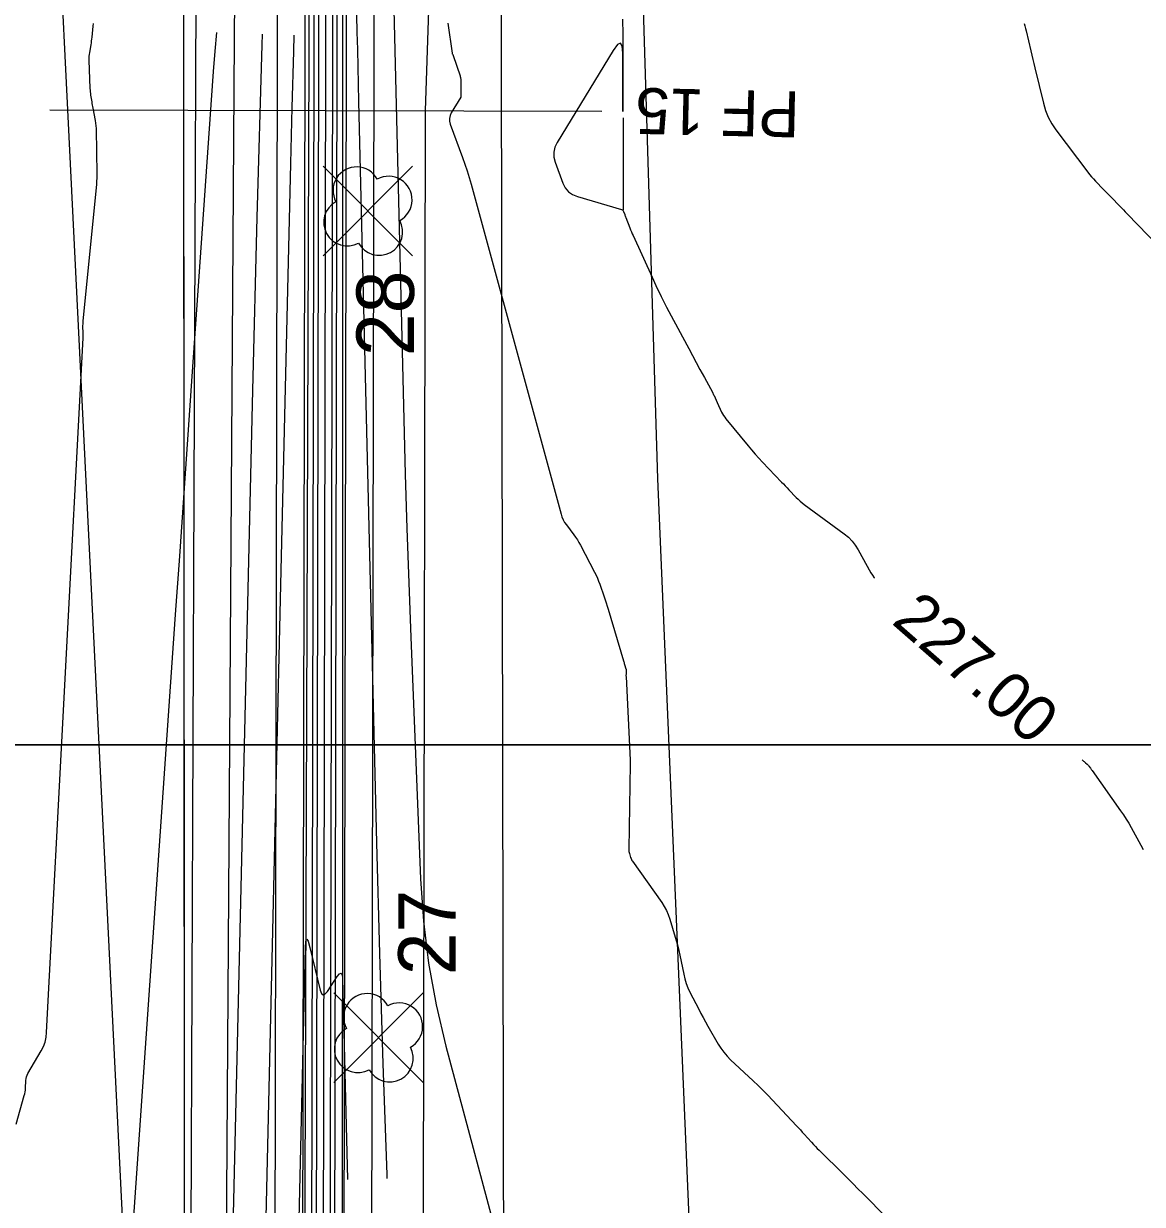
# Model space of a CAD drawing. Extents: x -534410 to -534262, y -1190162 to -1189584.
# Drawn here: x -534372.95 to -534348.63, y -1189804.46 to -1189778.79 of the extents above; entities that cross this region are included whole.
import ezdxf

# ---------------------------------------------------------------- set-up
doc = ezdxf.new("R2010")
doc.units = 0
for name, color, linetype in [('30', 7, 'Continuous'), ('31', 7, 'Continuous'), ('40', 7, 'Continuous'), ('_linie', 7, 'Continuous'), ('_N_osa', 7, 'Continuous'), ('_N_tenká', 7, 'Continuous'), ('_N_tenká_velmi', 7, 'Continuous'), ('_N_text', 7, 'Continuous'), ('_přístup', 7, 'Continuous'), ('_rámeček', 7, 'Continuous'), ('_tenka', 7, 'Continuous'), ('Default', 7, 'Continuous'), ('Hranice parcel', 7, 'Continuous')]:
    doc.layers.add(name, color=color, linetype=linetype)

msp = doc.modelspace()

# ---------------------------------------------------------------- linework, layer by layer
at = {"layer": '30'}
for points in [[(-534364.917, -1189777.897), (-534364.89, -1189779.084), (-534364.863, -1189780.271), (-534364.835, -1189781.459), (-534364.806, -1189782.646), (-534364.69, -1189787.402), (-534364.659, -1189788.586), (-534364.623, -1189789.769), (-534364.583, -1189790.952), (-534364.538, -1189792.135), (-534364.327, -1189797.385), (-534364.264, -1189798.305), (-534364.151, -1189799.218), (-534363.988, -1189800.123), (-534363.773, -1189801.02), (-534362.475, -1189805.863)], [(-534373.119, -1189802.721), (-534372.939, -1189802.098), (-534372.929, -1189802.057), (-534372.921, -1189802.017), (-534372.916, -1189801.976), (-534372.913, -1189801.935), (-534372.906, -1189801.768), (-534372.902, -1189801.728), (-534372.893, -1189801.688), (-534372.879, -1189801.65), (-534372.86, -1189801.614), (-534372.574, -1189801.126), (-534372.525, -1189801.031), (-534372.489, -1189800.933), (-534372.465, -1189800.83), (-534372.453, -1189800.724), (-534371.663, -1189785.627), (-534371.661, -1189785.597), (-534371.661, -1189785.567), (-534371.66, -1189785.537), (-534371.661, -1189785.507), (-534371.664, -1189785.386), (-534371.664, -1189785.356), (-534371.663, -1189785.326), (-534371.662, -1189785.296), (-534371.659, -1189785.266), (-534371.365, -1189782.288), (-534371.359, -1189782.22), (-534371.356, -1189782.153), (-534371.354, -1189782.085), (-534371.354, -1189782.017), (-534371.362, -1189781.623), (-534371.362, -1189781.597), (-534371.363, -1189781.558), (-534371.363, -1189781.545), (-534371.371, -1189781.129), (-534371.373, -1189781.072), (-534371.378, -1189781.015), (-534371.385, -1189780.959), (-534371.394, -1189780.902), (-534371.442, -1189780.635), (-534371.448, -1189780.6), (-534371.455, -1189780.564), (-534371.461, -1189780.529), (-534371.467, -1189780.493), (-534371.491, -1189780.351), (-534371.496, -1189780.316), (-534371.5, -1189780.28), (-534371.503, -1189780.244), (-534371.505, -1189780.208), (-534371.529, -1189779.589), (-534371.53, -1189779.547), (-534371.528, -1189779.505), (-534371.524, -1189779.463), (-534371.518, -1189779.421), (-534371.488, -1189779.255), (-534371.481, -1189779.213), (-534371.475, -1189779.172), (-534371.469, -1189779.13), (-534371.465, -1189779.088), (-534371.442, -1189778.847), (-534371.437, -1189778.793)], [(-534359.934, -1189778.7), (-534359.932, -1189778.799), (-534359.931, -1189778.844), (-534359.93, -1189778.89), (-534359.927, -1189778.982), (-534359.927, -1189779.005), (-534359.926, -1189779.028), (-534359.926, -1189779.05), (-534359.926, -1189779.073), (-534359.926, -1189780.616), (-534359.926, -1189780.639), (-534359.926, -1189780.661), (-534359.925, -1189780.684), (-534359.925, -1189780.707), (-534359.925, -1189780.684), (-534359.926, -1189780.661), (-534359.926, -1189780.639), (-534359.926, -1189780.616), (-534359.926, -1189779.436), (-534359.939, -1189779.279), (-534359.979, -1189779.217), (-534360.045, -1189779.249), (-534360.138, -1189779.377), (-534361.354, -1189781.377), (-534361.404, -1189781.481), (-534361.427, -1189781.588), (-534361.425, -1189781.697), (-534361.396, -1189781.809), (-534361.229, -1189782.262), (-534361.178, -1189782.365), (-534361.109, -1189782.448), (-534361.021, -1189782.512), (-534360.915, -1189782.555), (-534359.955, -1189782.835), (-534359.94, -1189782.841), (-534359.927, -1189782.85), (-534359.917, -1189782.862), (-534359.91, -1189782.877), (-534359.887, -1189782.943), (-534359.881, -1189782.96), (-534359.875, -1189782.976), (-534359.869, -1189782.993), (-534359.862, -1189783.009), (-534359.776, -1189783.234), (-534359.759, -1189783.277), (-534359.742, -1189783.319), (-534359.724, -1189783.362), (-534359.705, -1189783.403), (-534359.29, -1189784.304), (-534359.207, -1189784.484), (-534359.096, -1189784.724), (-534359.068, -1189784.784), (-534359.039, -1189784.844), (-534359.009, -1189784.903), (-534358.978, -1189784.961), (-534358.632, -1189785.602), (-534358.494, -1189785.858), (-534358.25, -1189786.31), (-534358.154, -1189786.488), (-534357.981, -1189786.808), (-534357.972, -1189786.826), (-534357.962, -1189786.845), (-534357.953, -1189786.863), (-534357.945, -1189786.882), (-534357.876, -1189787.032), (-534357.781, -1189787.238), (-534357.761, -1189787.278), (-534357.738, -1189787.317), (-534357.713, -1189787.353), (-534357.686, -1189787.389), (-534357.205, -1189787.971), (-534357.128, -1189788.062), (-534357.05, -1189788.152), (-534356.97, -1189788.24), (-534356.889, -1189788.327), (-534356.477, -1189788.761), (-534356.437, -1189788.802), (-534356.398, -1189788.844), (-534356.357, -1189788.886), (-534356.317, -1189788.928), (-534356.156, -1189789.094), (-534356.115, -1189789.135), (-534356.073, -1189789.174), (-534356.029, -1189789.211), (-534355.983, -1189789.246), (-534355.114, -1189789.888), (-534355.024, -1189789.961), (-534354.944, -1189790.043), (-534354.873, -1189790.133), (-534354.812, -1189790.231), (-534354.533, -1189790.732), (-534354.5, -1189790.787), (-534354.463, -1189790.839), (-534354.454, -1189790.851)], [(-534368.572, -1189812.408), (-534367.974, -1189786.766), (-534367.879, -1189783.012), (-534367.771, -1189779.259), (-534367.763, -1189779.023)], [(-534359.922, -1189780.845), (-534359.922, -1189782.845)], [(-534349.938, -1189794.801), (-534349.91, -1189794.827), (-534349.9, -1189794.836), (-534349.891, -1189794.844), (-534349.881, -1189794.853), (-534349.871, -1189794.861), (-534349.831, -1189794.895), (-534349.821, -1189794.904), (-534349.812, -1189794.913), (-534349.803, -1189794.923), (-534349.795, -1189794.933), (-534349.76, -1189794.981), (-534349.752, -1189794.992), (-534349.743, -1189795.004), (-534349.735, -1189795.015), (-534349.727, -1189795.027), (-534349.106, -1189795.905), (-534349.045, -1189795.995), (-534348.986, -1189796.086), (-534348.93, -1189796.178), (-534348.877, -1189796.273), (-534348.669, -1189796.654), (-534348.614, -1189796.748)], [(-534367.679, -1189830.441), (-534367.447, -1189823.822), (-534367.391, -1189822.167), (-534367.34, -1189820.512), (-534367.294, -1189818.856), (-534367.253, -1189817.201), (-534366.829, -1189798.889), (-534366.819, -1189798.744), (-534366.799, -1189798.695), (-534366.77, -1189798.739), (-534366.73, -1189798.878), (-534366.506, -1189799.806), (-534366.479, -1189799.878), (-534366.444, -1189799.907), (-534366.402, -1189799.892), (-534366.351, -1189799.834), (-534366.134, -1189799.511), (-534366.086, -1189799.452), (-534366.051, -1189799.438), (-534366.029, -1189799.469), (-534366.02, -1189799.544), (-534365.914, -1189803.919)]]:
    msp.add_lwpolyline(points, dxfattribs=at)
at = {"layer": '31'}
for points in [[(-534365.74, -1189777.481), (-534365.707, -1189778.983), (-534365.698, -1189779.359), (-534365.689, -1189779.735), (-534365.68, -1189780.11), (-534365.671, -1189780.486), (-534365.279, -1189796.604), (-534365.216, -1189799.007), (-534365.143, -1189801.409), (-534365.061, -1189803.811), (-534365.057, -1189803.898)], [(-534363.733, -1189778.785), (-534363.639, -1189779.439), (-534363.638, -1189779.443), (-534363.637, -1189779.448), (-534363.635, -1189779.452), (-534363.632, -1189779.456), (-534363.622, -1189779.471), (-534363.619, -1189779.475), (-534363.617, -1189779.479), (-534363.615, -1189779.484), (-534363.614, -1189779.488), (-534363.466, -1189779.93), (-534363.463, -1189779.94), (-534363.46, -1189779.95), (-534363.458, -1189779.96), (-534363.456, -1189779.97), (-534363.45, -1189780.011), (-534363.449, -1189780.021), (-534363.448, -1189780.031), (-534363.448, -1189780.041), (-534363.447, -1189780.052), (-534363.447, -1189780.314), (-534363.447, -1189780.331), (-534363.446, -1189780.365), (-534363.446, -1189780.382), (-534363.446, -1189780.386), (-534363.447, -1189780.39), (-534363.448, -1189780.394), (-534363.45, -1189780.397), (-534363.656, -1189780.736), (-534363.683, -1189780.794), (-534363.697, -1189780.854), (-534363.695, -1189780.915), (-534363.679, -1189780.978), (-534363.411, -1189781.707), (-534363.36, -1189781.85), (-534363.312, -1189781.994), (-534363.267, -1189782.139), (-534363.226, -1189782.285), (-534361.271, -1189789.455), (-534361.25, -1189789.518), (-534361.224, -1189789.579), (-534361.192, -1189789.636), (-534361.154, -1189789.691), (-534360.992, -1189789.905), (-534360.953, -1189789.959), (-534360.916, -1189790.015), (-534360.881, -1189790.072), (-534360.849, -1189790.131), (-534360.542, -1189790.717), (-534360.51, -1189790.781), (-534360.48, -1189790.847), (-534360.453, -1189790.913), (-534360.428, -1189790.98), (-534360.333, -1189791.252), (-534360.31, -1189791.32), (-534360.288, -1189791.388), (-534360.266, -1189791.456), (-534360.245, -1189791.525), (-534359.913, -1189792.647), (-534359.907, -1189792.667), (-534359.901, -1189792.686), (-534359.895, -1189792.706), (-534359.888, -1189792.726), (-534359.859, -1189792.817), (-534359.855, -1189792.831), (-534359.853, -1189792.845), (-534359.852, -1189792.859), (-534359.853, -1189792.874), (-534359.857, -1189792.932), (-534359.858, -1189792.947), (-534359.859, -1189792.961), (-534359.859, -1189792.976), (-534359.858, -1189792.99), (-534359.767, -1189794.809), (-534359.767, -1189794.815), (-534359.767, -1189794.821), (-534359.767, -1189794.828), (-534359.767, -1189794.834), (-534359.769, -1189794.859), (-534359.77, -1189794.871), (-534359.77, -1189794.884), (-534359.797, -1189796.744), (-534359.796, -1189796.767), (-534359.794, -1189796.79), (-534359.79, -1189796.812), (-534359.784, -1189796.834), (-534359.757, -1189796.923), (-534359.749, -1189796.945), (-534359.74, -1189796.965), (-534359.729, -1189796.986), (-534359.716, -1189797.005), (-534359.081, -1189797.899), (-534359.026, -1189797.984), (-534358.978, -1189798.072), (-534358.938, -1189798.164), (-534358.905, -1189798.26), (-534358.787, -1189798.65), (-534358.759, -1189798.747), (-534358.733, -1189798.846), (-534358.71, -1189798.945), (-534358.688, -1189799.044), (-534358.604, -1189799.459), (-534358.58, -1189799.56), (-534358.549, -1189799.659), (-534358.511, -1189799.755), (-534358.467, -1189799.849), (-534358.278, -1189800.219), (-534358.23, -1189800.312), (-534358.181, -1189800.403), (-534358.131, -1189800.494), (-534358.079, -1189800.585), (-534357.853, -1189800.976), (-534357.795, -1189801.069), (-534357.731, -1189801.157), (-534357.66, -1189801.24), (-534357.583, -1189801.318), (-534357.095, -1189801.777), (-534356.988, -1189801.879), (-534356.882, -1189801.983), (-534356.778, -1189802.089), (-534356.676, -1189802.196), (-534356.148, -1189802.757), (-534356.107, -1189802.801), (-534356.066, -1189802.845), (-534356.025, -1189802.889), (-534355.985, -1189802.934), (-534355.824, -1189803.113), (-534355.783, -1189803.157), (-534355.742, -1189803.201), (-534355.7, -1189803.244), (-534355.657, -1189803.287), (-534355.124, -1189803.815), (-534355.021, -1189803.917), (-534354.918, -1189804.019), (-534354.816, -1189804.122), (-534354.713, -1189804.225), (-534354.19, -1189804.755)], [(-534351.2, -1189778.79), (-534351.186, -1189778.845), (-534351.172, -1189778.9), (-534351.159, -1189778.955), (-534351.058, -1189779.39), (-534351.036, -1189779.481), (-534351.015, -1189779.572), (-534350.993, -1189779.663), (-534350.971, -1189779.754), (-534350.784, -1189780.526), (-534350.738, -1189780.682), (-534350.677, -1189780.83), (-534350.601, -1189780.972), (-534350.51, -1189781.106), (-534349.819, -1189782.026), (-534349.78, -1189782.076), (-534349.74, -1189782.125), (-534349.698, -1189782.172), (-534349.654, -1189782.218), (-534349.474, -1189782.402), (-534349.431, -1189782.446), (-534349.388, -1189782.49), (-534349.345, -1189782.534), (-534349.303, -1189782.578), (-534349.132, -1189782.756), (-534349.089, -1189782.8), (-534349.046, -1189782.844), (-534349.003, -1189782.889), (-534348.96, -1189782.933), (-534347.824, -1189784.101)], [(-534370.922, -1189809.965), (-534369.649, -1189791.643), (-534369.561, -1189790.374), (-534369.472, -1189789.105), (-534369.383, -1189787.836), (-534369.295, -1189786.567), (-534368.823, -1189779.835), (-534368.789, -1189779.394), (-534368.754, -1189778.99)], [(-534368.595, -1189844.62), (-534368.288, -1189828.137), (-534368.272, -1189827.381), (-534368.254, -1189826.626), (-534368.232, -1189825.87), (-534368.207, -1189825.115), (-534368.101, -1189822.093), (-534368.075, -1189821.337), (-534368.052, -1189820.581), (-534368.031, -1189819.826), (-534368.012, -1189819.07), (-534367.528, -1189798.201), (-534367.485, -1189796.321), (-534367.441, -1189794.441), (-534367.397, -1189792.561), (-534367.353, -1189790.681), (-534367.147, -1189781.836), (-534367.116, -1189780.619), (-534367.081, -1189779.401), (-534367.07, -1189779.047)]]:
    msp.add_lwpolyline(points, dxfattribs=at)
at = {"layer": '_linie'}
for points in [[(-534366.12, -1189620.81), (-534364.52, -1189627.2), (-534365.69, -1189653.8), (-534366.76, -1189684.81), (-534368.14, -1189748.73), (-534368.38, -1189779.14), (-534368.65, -1189820.64), (-534368.59, -1189847.58), (-534367.2, -1189913.8)], [(-534363.12, -1189621.02), (-534362.79, -1189621.58), (-534361.82, -1189627.79), (-534363.46, -1189653.55), (-534365.47, -1189684.77), (-534366.65, -1189748.83), (-534366.75, -1189779.47), (-534366.9, -1189820.47), (-534366.95, -1189846.72), (-534366.338, -1189888.804), (-534363.85, -1189911.95), (-534357.07, -1189929.19), (-534352.334, -1189940.856)], [(-534359.03, -1189621.26), (-534359.41, -1189621.83), (-534360.84, -1189627.76), (-534362.92, -1189653.56), (-534364.64, -1189685), (-534365.94, -1189748.9), (-534366.02, -1189779.52), (-534366.03, -1189820.5), (-534366.48, -1189846.73), (-534365.511, -1189888.873), (-534362.72, -1189912.12), (-534356.62, -1189928.64), (-534351.589, -1189940.594)]]:
    msp.add_lwpolyline(points, dxfattribs=at)
at = {"layer": '_N_osa'}
msp.add_lwpolyline([(-534351.95, -1189940.722), (-534356.845, -1189928.915), (-534363.285, -1189912.035), (-534365.925, -1189888.838), (-534366.715, -1189846.725), (-534366.465, -1189820.485), (-534366.385, -1189779.495), (-534366.295, -1189748.865), (-534365.055, -1189684.885), (-534363.19, -1189653.555), (-534361.333, -1189627.822)], dxfattribs=at)
at = {"layer": '_N_tenká'}
for points in [[(-534352.92, -1189941.124), (-534357.821, -1189929.303), (-534364.313, -1189912.285), (-534366.973, -1189888.908), (-534367.765, -1189846.73), (-534367.515, -1189820.479), (-534367.435, -1189779.492), (-534367.345, -1189748.853), (-534366.104, -1189684.844), (-534364.238, -1189653.486), (-534362.424, -1189628.352), (-534361.782, -1189627.792)], [(-534350.98, -1189940.319), (-534355.869, -1189928.527), (-534362.257, -1189911.785), (-534364.876, -1189888.769), (-534365.665, -1189846.72), (-534365.415, -1189820.491), (-534365.335, -1189779.498), (-534365.245, -1189748.877), (-534364.006, -1189684.926), (-534362.142, -1189653.624), (-534360.329, -1189628.488), (-534360.884, -1189627.851)]]:
    msp.add_lwpolyline(points, dxfattribs=at)
at = {"layer": '_N_tenká_velmi'}
for points in [[(-534352.366, -1189940.894), (-534357.263, -1189929.081), (-534363.726, -1189912.142), (-534366.374, -1189888.868), (-534367.165, -1189846.727), (-534366.915, -1189820.482), (-534366.835, -1189779.494), (-534366.745, -1189748.86), (-534365.505, -1189684.867), (-534363.639, -1189653.525), (-534361.782, -1189627.792)], [(-534352.181, -1189940.817), (-534357.077, -1189929.007), (-534363.53, -1189912.095), (-534366.174, -1189888.855), (-534366.965, -1189846.726), (-534366.715, -1189820.484), (-534366.635, -1189779.494), (-534366.545, -1189748.862), (-534365.305, -1189684.875), (-534363.439, -1189653.539), (-534361.583, -1189627.805)], [(-534352.089, -1189940.779), (-534356.984, -1189928.97), (-534363.432, -1189912.071), (-534366.074, -1189888.848), (-534366.865, -1189846.726), (-534366.615, -1189820.484), (-534366.535, -1189779.495), (-534366.445, -1189748.863), (-534365.205, -1189684.879), (-534363.34, -1189653.545), (-534361.483, -1189627.812)], [(-534351.812, -1189940.664), (-534356.706, -1189928.86), (-534363.138, -1189911.999), (-534365.775, -1189888.828), (-534366.565, -1189846.724), (-534366.315, -1189820.486), (-534366.235, -1189779.495), (-534366.145, -1189748.867), (-534364.905, -1189684.891), (-534363.04, -1189653.565), (-534361.184, -1189627.831)], [(-534351.719, -1189940.626), (-534356.613, -1189928.823), (-534363.04, -1189911.975), (-534365.675, -1189888.822), (-534366.465, -1189846.724), (-534366.215, -1189820.486), (-534366.135, -1189779.496), (-534366.045, -1189748.868), (-534364.805, -1189684.895), (-534362.941, -1189653.571), (-534361.084, -1189627.838)], [(-534351.534, -1189940.549), (-534356.427, -1189928.749), (-534362.844, -1189911.928), (-534365.475, -1189888.808), (-534366.265, -1189846.723), (-534366.015, -1189820.488), (-534365.935, -1189779.496), (-534365.845, -1189748.87), (-534364.605, -1189684.903), (-534362.741, -1189653.585), (-534360.884, -1189627.851)]]:
    msp.add_lwpolyline(points, dxfattribs=at)
at = {"layer": '_N_text'}
msp.add_lwpolyline([(-534360.387, -1189780.703), (-534372.387, -1189780.676)], dxfattribs=at)
at = {"layer": '_přístup'}
for p, q in [((-534364.497, -1189783.843), (-534366.443, -1189781.897)), ((-534366.443, -1189783.843), (-534364.497, -1189781.897)), ((-534364.267, -1189801.813), (-534366.213, -1189799.867)), ((-534366.213, -1189801.813), (-534364.267, -1189799.867))]:
    msp.add_line(p, q, dxfattribs=at)
for centre in [(-534365.47, -1189782.87), (-534365.24, -1189800.84)]:
    msp.add_circle(centre, 0.000512, dxfattribs=at)
for centre, start, end in [((-534365.715, -1189782.421), 28.6209, 208.6209), ((-534365.021, -1189782.625), 298.6209, 118.6209), ((-534365.919, -1189783.115), 118.6209, 298.6209), ((-534365.225, -1189783.319), 208.6209, 28.6209), ((-534365.485, -1189800.391), 28.6209, 208.6209), ((-534364.791, -1189800.595), 298.6209, 118.6209), ((-534365.689, -1189801.085), 118.6209, 298.6209), ((-534364.995, -1189801.289), 208.6209, 28.6209)]:
    msp.add_arc(centre, 0.512, start, end, dxfattribs=at)
at = {"layer": '_rámeček'}
for points in [[(-534410.126, -1189689.47), (-534261.626, -1189689.47), (-534261.626, -1189794.47), (-534410.126, -1189794.47)], [(-534410.126, -1189794.47), (-534261.626, -1189794.47), (-534261.626, -1189899.47), (-534410.126, -1189899.47)]]:
    msp.add_lwpolyline(points, close=True, dxfattribs=at)
at = {"layer": '_tenka'}
for points in [[(-534349.13, -1189939.73), (-534354.63, -1189926.96), (-534362.03, -1189907.65), (-534364.521, -1189888.74), (-534364.47, -1189846.64), (-534364.29, -1189820.63), (-534364.22, -1189780.69), (-534363.18, -1189749.38), (-534362.5, -1189685.39), (-534360.27, -1189651.6), (-534357.03, -1189627.34), (-534354.77, -1189620.37)], [(-534366.12, -1189620.81), (-534364.52, -1189627.2), (-534365.69, -1189653.8), (-534366.76, -1189684.81), (-534368.14, -1189748.73), (-534368.38, -1189779.14), (-534368.65, -1189820.64), (-534368.59, -1189847.58), (-534367.2, -1189913.8)], [(-534366.12, -1189620.81), (-534364.52, -1189627.2), (-534365.69, -1189653.8), (-534366.76, -1189684.81), (-534368.14, -1189748.73), (-534368.38, -1189779.14), (-534368.65, -1189820.64), (-534368.59, -1189847.58), (-534367.2, -1189913.8)], [(-534363.12, -1189621.02), (-534362.79, -1189621.58), (-534361.82, -1189627.79), (-534363.46, -1189653.55), (-534365.47, -1189684.77), (-534366.65, -1189748.83), (-534366.75, -1189779.47), (-534366.9, -1189820.47), (-534366.95, -1189846.72), (-534366.338, -1189888.804), (-534363.85, -1189911.95), (-534357.07, -1189929.19), (-534352.334, -1189940.856)], [(-534363.12, -1189621.02), (-534362.79, -1189621.58), (-534361.82, -1189627.79), (-534363.46, -1189653.55), (-534365.47, -1189684.77), (-534366.65, -1189748.83), (-534366.75, -1189779.47), (-534366.9, -1189820.47), (-534366.95, -1189846.72), (-534366.338, -1189888.804), (-534363.85, -1189911.95), (-534357.07, -1189929.19), (-534352.334, -1189940.856)], [(-534359.03, -1189621.26), (-534359.41, -1189621.83), (-534360.84, -1189627.76), (-534362.92, -1189653.56), (-534364.64, -1189685), (-534365.94, -1189748.9), (-534366.02, -1189779.52), (-534366.03, -1189820.5), (-534366.48, -1189846.73), (-534365.511, -1189888.873), (-534362.72, -1189912.12), (-534356.62, -1189928.64), (-534351.589, -1189940.594)], [(-534359.03, -1189621.26), (-534359.41, -1189621.83), (-534360.84, -1189627.76), (-534362.92, -1189653.56), (-534364.64, -1189685), (-534365.94, -1189748.9), (-534366.02, -1189779.52), (-534366.03, -1189820.5), (-534366.48, -1189846.73), (-534365.511, -1189888.873), (-534362.72, -1189912.12), (-534356.62, -1189928.64), (-534351.589, -1189940.594)], [(-534368.65, -1189626.81), (-534368.65, -1189626.81), (-534367.31, -1189654.04), (-534367.67, -1189685.23), (-534369.56, -1189748.93), (-534369.48, -1189778.6), (-534369.45, -1189820.62), (-534369.45, -1189847.87), (-534371.206, -1189896.071), (-534372.39, -1189914.47)]]:
    msp.add_lwpolyline(points, dxfattribs=at)
at = {"layer": 'Default'}
msp.add_line((-534369.48, -1189778.6), (-534369.45, -1189820.62), dxfattribs=at)
msp.add_lwpolyline([(-534349.13, -1189939.73), (-534354.63, -1189926.96), (-534362.03, -1189907.65), (-534364.521, -1189888.74), (-534364.47, -1189846.64), (-534364.29, -1189820.63), (-534364.22, -1189780.69), (-534363.18, -1189749.38), (-534362.5, -1189685.39), (-534360.27, -1189651.6), (-534357.03, -1189627.34), (-534354.77, -1189620.37)], dxfattribs=at)
at = {"layer": 'Hranice parcel'}
msp.add_line((-534369.38, -1189820.8), (-534369.14, -1189764.19), dxfattribs=at)
for points in [[(-534359.48, -1189697.97), (-534362.6, -1189764.35), (-534362.34, -1189901.56)], [(-534359.48, -1189697.97), (-534360.42, -1189747.8), (-534359.17, -1189788.69), (-534356.86, -1189843.2), (-534358.53, -1189915.98)], [(-534369.38, -1189820.8), (-534370.35, -1189813.98), (-534372.65, -1189767.31), (-534373.49, -1189759.21)]]:
    msp.add_lwpolyline(points, dxfattribs=at)

# ---------------------------------------------------------------- texts
at = {"layer": '40'}
msp.add_text('227.00', height=1, rotation=318.8345, dxfattribs=at).set_placement((-534354.108, -1189791.819))
at = {"layer": '_N_text'}
msp.add_text('PF 15', height=1, rotation=178.6938, dxfattribs=at).set_placement((-534356.073, -1189780.272))
at = {"layer": '_přístup'}
for s, p in [('28', (-534364.468, -1189786.022)), ('27', (-534363.56, -1189799.481))]:
    msp.add_text(s, height=1.25, rotation=90, dxfattribs=at).set_placement(p)

doc.saveas('drawing.dxf')
